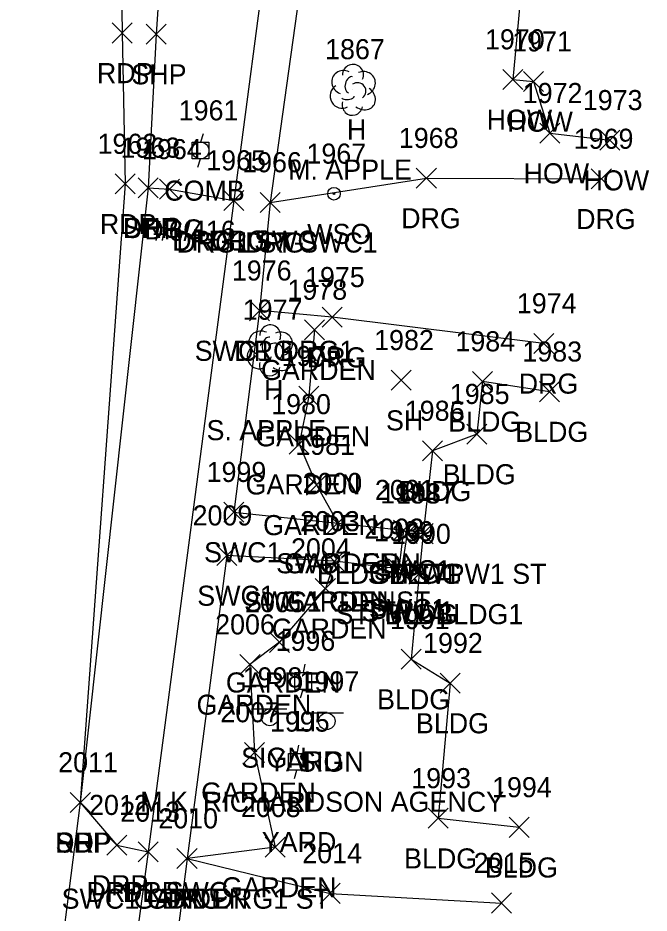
# Model space of a CAD drawing. Extents: x 1651305 to 1654558, y 539481 to 548441.
# Drawn here: x 1654391.1 to 1654454.1, y 544348.7 to 544437.8 of the extents above; entities that cross this region are included whole.
import ezdxf

# ---------------------------------------------------------------- set-up
doc = ezdxf.new("R2010")
doc.units = 0
for name, color, linetype in [('L_A', 7, 'Continuous'), ('L_C', 7, 'Continuous'), ('L_I', 7, 'Continuous'), ('L_TIC', 7, 'Continuous'), ('LAPB', 7, 'Continuous'), ('LBC', 7, 'Continuous'), ('LBF', 7, 'Continuous'), ('LTD', 7, 'Continuous'), ('P_A', 7, 'Continuous'), ('P_I', 7, 'Continuous'), ('P_TIC', 7, 'Continuous'), ('PET', 7, 'Continuous'), ('PSP', 7, 'Continuous'), ('R_A', 7, 'Continuous'), ('R_I', 7, 'Continuous'), ('R_TIC', 7, 'Continuous'), ('RDG', 7, 'Continuous'), ('RDP', 7, 'Continuous'), ('RSW', 7, 'Continuous'), ('S_A', 7, 'Continuous'), ('S_C', 7, 'Continuous'), ('S_I', 7, 'Continuous'), ('SSGN', 7, 'Continuous'), ('U_A', 7, 'Continuous'), ('U_C', 7, 'Continuous'), ('U_I', 7, 'Continuous'), ('ULP', 7, 'Continuous'), ('UP', 7, 'Continuous'), ('UWV', 7, 'Continuous')]:
    doc.layers.add(name, color=color, linetype=linetype)

msp = doc.modelspace()

# ---------------------------------------------------------------- linework, layer by layer
at = {"layer": 'L_TIC'}
for points in [[(1654439.479, 544430.714), (1654441.479, 544432.714)], [(1654441.479, 544430.714), (1654439.479, 544432.714)], [(1654441.535, 544430.51), (1654443.535, 544432.51)], [(1654443.535, 544430.51), (1654441.535, 544432.51)], [(1654443.157, 544425.366), (1654445.157, 544427.366)], [(1654445.157, 544425.366), (1654443.157, 544427.366)], [(1654449.144, 544424.661), (1654451.144, 544426.661)], [(1654451.144, 544424.661), (1654449.144, 544426.661)], [(1654419.708, 544405.771), (1654421.708, 544407.771)], [(1654421.708, 544405.771), (1654419.708, 544407.771)], [(1654428.347, 544400.756), (1654430.347, 544402.756)], [(1654430.347, 544400.756), (1654428.347, 544402.756)], [(1654436.446, 544400.633), (1654438.446, 544402.633)], [(1654438.446, 544400.633), (1654436.446, 544402.633)], [(1654419.132, 544399.165), (1654421.132, 544401.165)], [(1654421.132, 544399.165), (1654419.132, 544401.165)], [(1654443.12, 544399.614), (1654445.12, 544401.614)], [(1654445.12, 544399.614), (1654443.12, 544401.614)], [(1654435.894, 544395.387), (1654437.894, 544397.387)], [(1654437.894, 544395.387), (1654435.894, 544397.387)], [(1654418.173, 544394.372), (1654420.173, 544396.372)], [(1654420.173, 544394.372), (1654418.173, 544396.372)], [(1654431.456, 544393.71), (1654433.456, 544395.71)], [(1654433.456, 544393.71), (1654431.456, 544395.71)], [(1654419.916, 544390.32), (1654421.916, 544392.32)], [(1654421.916, 544390.32), (1654419.916, 544392.32)], [(1654422.018, 544386.519), (1654424.018, 544388.519)], [(1654424.018, 544386.519), (1654422.018, 544388.519)], [(1654428.943, 544385.479), (1654430.943, 544387.479)], [(1654430.943, 544385.479), (1654428.943, 544387.479)], [(1654430.537, 544385.471), (1654432.537, 544387.471)], [(1654432.537, 544385.471), (1654430.537, 544387.471)], [(1654430.537, 544385.471), (1654432.537, 544387.471)], [(1654432.537, 544385.471), (1654430.537, 544387.471)], [(1654421.687, 544382.714), (1654423.687, 544384.714)], [(1654423.687, 544382.714), (1654421.687, 544384.714)], [(1654428.343, 544381.719), (1654430.343, 544383.719)], [(1654430.343, 544381.719), (1654428.343, 544383.719)], [(1654430.125, 544381.453), (1654432.125, 544383.453)], [(1654432.125, 544381.453), (1654430.125, 544383.453)], [(1654430.125, 544381.453), (1654432.125, 544383.453)], [(1654432.125, 544381.453), (1654430.125, 544383.453)], [(1654420.789, 544380.007), (1654422.789, 544382.007)], [(1654422.789, 544380.007), (1654420.789, 544382.007)], [(1654416.206, 544374.646), (1654418.206, 544376.646)], [(1654418.206, 544374.646), (1654416.206, 544376.646)], [(1654413.279, 544372.431), (1654415.279, 544374.431)], [(1654415.279, 544372.431), (1654413.279, 544374.431)], [(1654429.354, 544372.968), (1654431.354, 544374.968)], [(1654431.354, 544372.968), (1654429.354, 544374.968)], [(1654433.226, 544370.582), (1654435.226, 544372.582)], [(1654435.226, 544370.582), (1654433.226, 544372.582)], [(1654413.737, 544363.68), (1654415.737, 544365.68)], [(1654415.737, 544363.68), (1654413.737, 544365.68)], [(1654432.046, 544357.115), (1654434.046, 544359.115)], [(1654434.046, 544357.115), (1654432.046, 544359.115)], [(1654440.097, 544356.215), (1654442.097, 544358.215)], [(1654442.097, 544356.215), (1654440.097, 544358.215)], [(1654415.795, 544354.239), (1654417.795, 544356.239)], [(1654417.795, 544354.239), (1654415.795, 544356.239)], [(1654407, 544353.107), (1654409, 544355.107)], [(1654409, 544353.107), (1654407, 544355.107)]]:
    msp.add_lwpolyline(points, dxfattribs=at)
at = {"layer": 'LAPB'}
for points in [[(1654420.708, 544406.771), (1654420.132, 544400.165), (1654419.173, 544395.372), (1654420.916, 544391.32), (1654423.018, 544387.519)], [(1654422.687, 544383.714), (1654421.789, 544381.007), (1654417.206, 544375.646), (1654414.279, 544373.431), (1654414.737, 544364.68), (1654416.795, 544355.239), (1654408, 544354.107)]]:
    msp.add_lwpolyline(points, dxfattribs=at)
at = {"layer": 'LBC'}
for points in [[(1654450.965, 544465.468), (1654444.011, 544466.184), (1654442.811, 544454.213), (1654441.59, 544443.825), (1654440.479, 544431.714), (1654442.535, 544431.51), (1654444.157, 544426.366), (1654450.144, 544425.661)], [(1654444.12, 544400.614), (1654437.446, 544401.633), (1654436.894, 544396.387), (1654432.456, 544394.71), (1654431.537, 544386.471), (1654431.125, 544382.453), (1654430.354, 544373.968), (1654434.226, 544371.582), (1654433.046, 544358.115), (1654441.097, 544357.215)]]:
    msp.add_lwpolyline(points, dxfattribs=at)
at = {"layer": 'LBF'}
msp.add_lwpolyline([(1654431.537, 544386.471), (1654429.943, 544386.479), (1654429.343, 544382.719), (1654431.125, 544382.453)], dxfattribs=at)
at = {"layer": 'LTD'}
for p, q in [((1654424.505, 544430.733), (1654424.505, 544430.733)), ((1654424.505, 544430.733), (1654424.505, 544430.733)), ((1654416.25, 544404.781), (1654416.25, 544404.781)), ((1654416.25, 544404.781), (1654416.25, 544404.781))]:
    msp.add_line(p, q, dxfattribs=at)
for centre in [(1654424.552, 544432.167), (1654416.296, 544406.215)]:
    msp.add_arc(centre, 1.047, 335.52715, 180.95627, dxfattribs=at)
for centre, major_axis, ratio, start_param, end_param in [((1654423.713, 544431.399), (1.21, -0.512), 0.895232, 1.570796, 4.712389), ((1654425.547, 544431.316), (-1.141, -0.483), 0.949671, 1.570796, 4.712389), ((1654424.297, 544431.191), (-0.208, -0.792), 0.645439, 3.141593, 6.283185), ((1654425.005, 544430.566), (-0.5, 0.667), 0.989748, 3.141593, 6.283185), ((1654423.422, 544430.024), (0.584, -1.042), 0.959034, 3.141593, 6.283185), ((1654425.505, 544429.9), (-1.09, 0.792), 0.841452, 1.570796, 4.712389), ((1654424.047, 544429.983), (-0.625, -0.083), 0.423636, 0, 3.141593), ((1654424.505, 544429.233), (0.265, 1.061), 0.942809, 1.570796, 4.712389), ((1654415.458, 544405.448), (1.21, -0.512), 0.895232, 1.570796, 4.712389), ((1654417.291, 544405.365), (-1.141, -0.483), 0.949671, 1.570796, 4.712389), ((1654416.041, 544405.24), (-0.208, -0.792), 0.645439, 3.141593, 6.283185), ((1654415.166, 544404.073), (0.584, -1.042), 0.959034, 3.141593, 6.283185), ((1654416.75, 544404.615), (-0.5, 0.667), 0.989748, 3.141593, 6.283185), ((1654417.25, 544403.948), (-1.09, 0.792), 0.841452, 1.570796, 4.712389), ((1654415.791, 544404.031), (-0.625, -0.083), 0.423636, 0, 3.141593), ((1654416.25, 544403.281), (0.265, 1.061), 0.942809, 1.570796, 4.712389)]:
    msp.add_ellipse(centre, major_axis=major_axis, ratio=ratio, start_param=start_param, end_param=end_param, dxfattribs=at)
at = {"layer": 'P_TIC'}
for points in [[(1654400.531, 544435.346), (1654402.531, 544437.346)], [(1654402.531, 544435.346), (1654400.531, 544437.346)], [(1654403.923, 544435.226), (1654405.923, 544437.226)], [(1654405.923, 544435.226), (1654403.923, 544437.226)], [(1654400.825, 544420.309), (1654402.825, 544422.309)], [(1654402.825, 544420.309), (1654400.825, 544422.309)], [(1654403.117, 544419.923), (1654405.117, 544421.923)], [(1654405.117, 544419.923), (1654403.117, 544421.923)], [(1654396.366, 544358.696), (1654398.366, 544360.696)], [(1654398.366, 544358.696), (1654396.366, 544360.696)], [(1654396.366, 544358.696), (1654398.366, 544360.696)], [(1654398.366, 544358.696), (1654396.366, 544360.696)]]:
    msp.add_lwpolyline(points, dxfattribs=at)
at = {"layer": 'PET'}
msp.add_lwpolyline([(1654345.042, 544588.36), (1654350.59, 544607.191), (1654356.582, 544624.309), (1654366.692, 544597.705), (1654378.699, 544565.627), (1654388.798, 544536.019), (1654394.392, 544506.433), (1654399.121, 544481.008), (1654401.125, 544462.893), (1654401.531, 544436.346), (1654401.825, 544421.309), (1654397.366, 544359.696), (1654394.392, 544336.586), (1654391.404, 544308.963), (1654388.941, 544290.736), (1654386.845, 544274.06), (1654380.974, 544229.445), (1654377.749, 544202.908), (1654375.628, 544181.037), (1654372.192, 544149.754), (1654366.612, 544105.723), (1654362.798, 544072.788)], dxfattribs=at)
at = {"layer": 'PSP'}
msp.add_lwpolyline([(1654388.798, 544536.019), (1654393.152, 544530.334), (1654397.052, 544530.18), (1654401.661, 544509.48), (1654405.45, 544481.191), (1654406.951, 544466.687), (1654404.923, 544436.226), (1654404.117, 544420.923), (1654397.366, 544359.696)], dxfattribs=at)
at = {"layer": 'R_TIC'}
for points in [[(1654430.857, 544420.889), (1654432.857, 544422.889)], [(1654432.857, 544420.889), (1654430.857, 544422.889)], [(1654448.296, 544420.81), (1654450.296, 544422.81)], [(1654450.296, 544420.81), (1654448.296, 544422.81)], [(1654403.117, 544419.923), (1654405.117, 544421.923)], [(1654405.117, 544419.923), (1654403.117, 544421.923)], [(1654405.26, 544419.775), (1654407.26, 544421.775)], [(1654407.26, 544419.775), (1654405.26, 544421.775)], [(1654411.659, 544418.662), (1654413.659, 544420.662)], [(1654413.659, 544418.662), (1654411.659, 544420.662)], [(1654411.659, 544418.662), (1654413.659, 544420.662)], [(1654413.659, 544418.662), (1654411.659, 544420.662)], [(1654415.298, 544418.47), (1654417.298, 544420.47)], [(1654417.298, 544418.47), (1654415.298, 544420.47)], [(1654415.298, 544418.47), (1654417.298, 544420.47)], [(1654417.298, 544418.47), (1654415.298, 544420.47)], [(1654414.224, 544407.685), (1654416.224, 544409.685)], [(1654416.224, 544407.685), (1654414.224, 544409.685)], [(1654414.224, 544407.685), (1654416.224, 544409.685)], [(1654416.224, 544407.685), (1654414.224, 544409.685)], [(1654421.456, 544407.031), (1654423.456, 544409.031)], [(1654423.456, 544407.031), (1654421.456, 544409.031)], [(1654442.572, 544404.42), (1654444.572, 544406.42)], [(1654444.572, 544404.42), (1654442.572, 544406.42)], [(1654411.657, 544387.617), (1654413.657, 544389.617)], [(1654413.657, 544387.617), (1654411.657, 544389.617)], [(1654422.018, 544386.519), (1654424.018, 544388.519)], [(1654424.018, 544386.519), (1654422.018, 544388.519)], [(1654428.579, 544385.827), (1654430.579, 544387.827)], [(1654430.579, 544385.827), (1654428.579, 544387.827)], [(1654410.983, 544383.286), (1654412.983, 544385.286)], [(1654412.983, 544383.286), (1654410.983, 544385.286)], [(1654421.687, 544382.714), (1654423.687, 544384.714)], [(1654423.687, 544382.714), (1654421.687, 544384.714)], [(1654428.097, 544381.97), (1654430.097, 544383.97)], [(1654430.097, 544381.97), (1654428.097, 544383.97)], [(1654396.366, 544358.696), (1654398.366, 544360.696)], [(1654398.366, 544358.696), (1654396.366, 544360.696)], [(1654400.014, 544354.446), (1654402.014, 544356.446)], [(1654402.014, 544354.446), (1654400.014, 544356.446)], [(1654403.122, 544353.774), (1654405.122, 544355.774)], [(1654405.122, 544353.774), (1654403.122, 544355.774)], [(1654403.122, 544353.774), (1654405.122, 544355.774)], [(1654405.122, 544353.774), (1654403.122, 544355.774)], [(1654407, 544353.107), (1654409, 544355.107)], [(1654409, 544353.107), (1654407, 544355.107)], [(1654407, 544353.107), (1654409, 544355.107)], [(1654409, 544353.107), (1654407, 544355.107)], [(1654421.263, 544349.637), (1654423.263, 544351.637)], [(1654423.263, 544349.637), (1654421.263, 544351.637)], [(1654438.341, 544348.676), (1654440.341, 544350.676)], [(1654440.341, 544348.676), (1654438.341, 544350.676)]]:
    msp.add_lwpolyline(points, dxfattribs=at)
at = {"layer": 'RDG'}
for points in [[(1654416.298, 544419.47), (1654431.857, 544421.889), (1654449.296, 544421.81)], [(1654404.117, 544420.923), (1654406.26, 544420.775), (1654412.659, 544419.662)], [(1654443.572, 544405.42), (1654422.456, 544408.031), (1654415.224, 544408.685)], [(1654408, 544354.107), (1654422.263, 544350.637), (1654439.341, 544349.676)]]:
    msp.add_lwpolyline(points, dxfattribs=at)
at = {"layer": 'RDP'}
msp.add_lwpolyline([(1654397.366, 544359.696), (1654401.014, 544355.446), (1654404.122, 544354.774)], dxfattribs=at)
at = {"layer": 'RSW'}
for points in [[(1654407.404, 544661.775), (1654407.293, 544658.868), (1654407.962, 544657.877), (1654443.269, 544654.592), (1654438.81, 544619.894), (1654433.558, 544580.17), (1654430.136, 544553.995), (1654428.025, 544537.281), (1654424.833, 544512.838), (1654419.77, 544473.615), (1654412.659, 544419.662), (1654404.122, 544354.774), (1654402.102, 544339.773), (1654395.487, 544286.058), (1654394.013, 544276.122), (1654388.386, 544229.583), (1654383.891, 544196.376), (1654382.201, 544184.333), (1654378.352, 544149.148), (1654372.361, 544105.495), (1654368.546, 544072.052)], [(1654433.769, 544447.317), (1654420.392, 544448.732), (1654416.298, 544419.47), (1654415.224, 544408.685), (1654412.657, 544388.617), (1654423.018, 544387.519), (1654429.579, 544386.827), (1654429.097, 544382.97), (1654422.687, 544383.714), (1654411.983, 544384.286), (1654408, 544354.107), (1654405.993, 544338.287), (1654403.211, 544318.213), (1654402.851, 544314.962), (1654399.432, 544285.106), (1654398.089, 544275.966), (1654392.335, 544231.256), (1654397.808, 544230.762), (1654412.219, 544229.296)]]:
    msp.add_lwpolyline(points, dxfattribs=at)
at = {"layer": 'SSGN'}
for p, q in [((1654414.608, 544369.007), (1654417.942, 544369.007)), ((1654416.255, 544368.173), (1654416.255, 544368.173)), ((1654420.281, 544368.612), (1654423.614, 544368.612)), ((1654421.928, 544367.779), (1654421.928, 544367.779))]:
    msp.add_line(p, q, dxfattribs=at)
for centre in [(1654416.255, 544368.173), (1654421.928, 544367.779)]:
    msp.add_circle(centre, 0.833, dxfattribs=at)
at = {"layer": 'ULP'}
for p, q in [((1654418.745, 544370.958), (1654418.745, 544372.624)), ((1654418.745, 544372.624), (1654420.412, 544372.624)), ((1654419.745, 544373.458), (1654419.578, 544372.624)), ((1654420.412, 544372.624), (1654420.412, 544370.958)), ((1654419.578, 544371.791), (1654419.578, 544371.791)), ((1654420.412, 544370.958), (1654418.745, 544370.958)), ((1654419.328, 544370.124), (1654419.578, 544370.958)), ((1654418.125, 544362.911), (1654418.125, 544364.578)), ((1654418.125, 544364.578), (1654419.792, 544364.578)), ((1654419.125, 544365.411), (1654418.959, 544364.578)), ((1654419.792, 544364.578), (1654419.792, 544362.911)), ((1654418.959, 544363.745), (1654418.959, 544363.745)), ((1654419.792, 544362.911), (1654418.125, 544362.911)), ((1654418.709, 544362.078), (1654418.959, 544362.911))]:
    msp.add_line(p, q, dxfattribs=at)
at = {"layer": 'UP'}
for p, q in [((1654409.596, 544426.306), (1654409.346, 544425.473)), ((1654408.513, 544423.806), (1654408.513, 544425.473)), ((1654408.513, 544425.473), (1654410.179, 544425.473)), ((1654410.179, 544425.473), (1654410.179, 544423.806)), ((1654409.346, 544424.64), (1654409.346, 544424.64)), ((1654410.179, 544423.806), (1654408.513, 544423.806)), ((1654409.096, 544422.973), (1654409.346, 544423.806))]:
    msp.add_line(p, q, dxfattribs=at)
msp.add_circle((1654409.346, 544424.64), 0.833, dxfattribs=at)
at = {"layer": 'UWV'}
for radius in [0.625, 0.0833]:
    msp.add_circle((1654422.647, 544420.329), radius, dxfattribs=at)

# ---------------------------------------------------------------- texts
at = {"layer": 'L_A'}
for s, p in [('HOW', (1654437.864, 544426.714)), ('HOW', (1654439.921, 544426.51)), ('H', (1654423.938, 544425.733)), ('HOW', (1654441.543, 544421.366)), ('HOW', (1654447.53, 544420.661)), ('GARDEN', (1654415.377, 544401.771)), ('H', (1654415.683, 544399.781)), ('SH', (1654427.835, 544396.756)), ('BLDG', (1654434.036, 544396.633)), ('BLDG', (1654440.711, 544395.614)), ('GARDEN', (1654414.801, 544395.165)), ('BLDG', (1654433.484, 544391.387)), ('GARDEN', (1654413.842, 544390.372)), ('BLDG', (1654429.046, 544389.71)), ('GARDEN', (1654415.586, 544386.32)), ('GARDEN', (1654417.687, 544382.519)), ('BLDG1 STPW1 ST', (1654420.947, 544381.471)), ('STPW1', (1654426.006, 544381.479)), ('BLDG', (1654428.128, 544381.471)), ('GARDEN', (1654417.356, 544378.714)), ('STPW1', (1654425.406, 544377.719)), ('STPW1 BLDG1', (1654422.795, 544377.453)), ('BLDG', (1654427.716, 544377.453)), ('GARDEN', (1654416.458, 544376.007)), ('GARDEN', (1654411.875, 544370.646)), ('BLDG', (1654426.944, 544368.968)), ('GARDEN', (1654408.949, 544368.431)), ('BLDG', (1654430.816, 544366.582)), ('GARDEN', (1654409.406, 544359.68)), ('BLDG', (1654429.636, 544353.115)), ('BLDG', (1654437.687, 544352.215)), ('GARDEN', (1654411.464, 544350.239)), ('GARDEN', (1654402.669, 544349.107))]:
    msp.add_text(s, height=2, dxfattribs=at).set_placement(p)
at = {"layer": 'L_C'}
for s, p in [('M. APPLE', (1654418.08, 544421.733)), ('S. APPLE', (1654409.95, 544395.781))]:
    msp.add_text(s, height=2, dxfattribs=at).set_placement(p)
at = {"layer": 'L_I'}
for s, p in [('1970', (1654437.699, 544434.714)), ('1971', (1654440.409, 544434.51)), ('1867', (1654421.765, 544433.733)), ('1972', (1654441.465, 544429.366)), ('1973', (1654447.452, 544428.661)), ('1978', (1654418.015, 544409.771)), ('1977', (1654413.557, 544407.781)), ('1982', (1654426.654, 544404.756)), ('1984', (1654434.753, 544404.633)), ('1983', (1654441.427, 544403.614)), ('1979', (1654417.431, 544403.165)), ('1985', (1654434.201, 544399.387)), ('1980', (1654416.394, 544398.372)), ('1986', (1654429.708, 544397.71)), ('1981', (1654418.791, 544394.32)), ('2000', (1654419.514, 544390.519)), ('1988', (1654427.25, 544389.479)), ('1987', (1654428.845, 544389.471)), ('1987', (1654428.845, 544389.471)), ('2003', (1654419.27, 544386.714)), ('1989', (1654426.643, 544385.719)), ('1990', (1654428.346, 544385.453)), ('1990', (1654428.346, 544385.453)), ('2004', (1654418.371, 544384.007)), ('2005', (1654413.789, 544378.646)), ('1991', (1654428.228, 544376.968)), ('2006', (1654410.807, 544376.431)), ('1992', (1654431.533, 544374.582)), ('2007', (1654411.319, 544367.68)), ('1993', (1654430.353, 544361.115)), ('1994', (1654438.404, 544360.215)), ('2008', (1654413.378, 544358.239)), ('2010', (1654405.142, 544357.107))]:
    msp.add_text(s, height=2, dxfattribs=at).set_placement(p)
at = {"layer": 'P_A'}
for s, p in [('RDP', (1654399.019, 544431.346)), ('SHP', (1654402.458, 544431.226)), ('RDP', (1654399.314, 544416.309)), ('SHP', (1654401.653, 544415.923)), ('SHP', (1654394.901, 544354.696)), ('RDP', (1654394.854, 544354.696))]:
    msp.add_text(s, height=2, dxfattribs=at).set_placement(p)
at = {"layer": 'P_I'}
for s, p in [('1962', (1654399.085, 544424.309)), ('1963', (1654401.377, 544423.923)), ('2011', (1654395.161, 544362.696)), ('2011', (1654395.161, 544362.696))]:
    msp.add_text(s, height=2, dxfattribs=at).set_placement(p)
at = {"layer": 'R_A'}
for s, p in [('DRG', (1654429.345, 544416.889)), ('DRG', (1654446.784, 544416.81)), ('DRG', (1654401.606, 544415.923)), ('DRG', (1654403.748, 544415.775)), ('DRG1 SWC', (1654406.525, 544414.662)), ('DRG1 ST SWC1', (1654406.944, 544414.47)), ('DRG', (1654410.147, 544414.662)), ('DRG', (1654413.786, 544414.47)), ('SWC1 DRG1', (1654408.768, 544403.685)), ('DRG', (1654412.712, 544403.685)), ('DRG', (1654419.944, 544403.031)), ('DRG', (1654441.06, 544400.42)), ('SWC1', (1654409.696, 544383.617)), ('SWC1 GDN', (1654416.884, 544382.519)), ('SWC1', (1654426.618, 544381.827)), ('SWC1', (1654409.022, 544379.286)), ('SWC1 GDN ST', (1654413.687, 544378.714)), ('SWC1', (1654426.136, 544377.97)), ('DRP', (1654394.854, 544354.696)), ('DRP', (1654398.502, 544350.446)), ('DRP1 SWC', (1654397.989, 544349.774)), ('DRP', (1654401.611, 544349.774)), ('SWC1 GDN DRG1 ST', (1654395.504, 544349.107)), ('DRG', (1654405.488, 544349.107))]:
    msp.add_text(s, height=2, dxfattribs=at).set_placement(p)
at = {"layer": 'R_I'}
for s, p in [('1968', (1654429.117, 544424.889)), ('1969', (1654446.548, 544424.81)), ('1963', (1654401.377, 544423.923)), ('1964', (1654403.52, 544423.775)), ('1965', (1654409.919, 544422.662)), ('1965', (1654409.919, 544422.662)), ('1966', (1654413.503, 544422.47)), ('1966', (1654413.503, 544422.47)), ('1976', (1654412.476, 544411.685)), ('1976', (1654412.476, 544411.685)), ('1975', (1654419.763, 544411.031)), ('1974', (1654440.879, 544408.42)), ('1999', (1654409.956, 544391.617)), ('2000', (1654419.514, 544390.519)), ('2001', (1654426.728, 544389.827)), ('2009', (1654408.558, 544387.286)), ('2003', (1654419.27, 544386.714)), ('2002', (1654425.68, 544385.97)), ('2011', (1654395.161, 544362.696)), ('2012', (1654398.242, 544358.446)), ('2013', (1654401.351, 544357.774)), ('2013', (1654401.351, 544357.774)), ('2010', (1654405.142, 544357.107)), ('2010', (1654405.142, 544357.107)), ('2014', (1654419.492, 544353.637)), ('2015', (1654436.57, 544352.676))]:
    msp.add_text(s, height=2, dxfattribs=at).set_placement(p)
at = {"layer": 'S_A'}
for p in [(1654413.393, 544363.153), (1654419.066, 544362.759)]:
    msp.add_text('SIGN', height=2, dxfattribs=at).set_placement(p)
at = {"layer": 'S_C'}
msp.add_text('M.K. RICHARDSON AGENCY', height=2, dxfattribs=at).set_placement((1654403.342, 544358.759))
at = {"layer": 'S_I'}
for s, p in [('1998', (1654413.543, 544371.153)), ('1997', (1654419.216, 544370.759))]:
    msp.add_text(s, height=2, dxfattribs=at).set_placement(p)
at = {"layer": 'U_A'}
for s, p in [('COMB', (1654405.732, 544419.64)), ('WSO', (1654419.978, 544415.329)), ('LI', (1654418.681, 544366.791)), ('LI', (1654418.061, 544358.745))]:
    msp.add_text(s, height=2, dxfattribs=at).set_placement(p)
at = {"layer": 'U_C'}
for s, p in [('#6/416', (1654404.677, 544415.64)), ('YARD', (1654416.074, 544362.791)), ('YARD', (1654415.455, 544354.745))]:
    msp.add_text(s, height=2, dxfattribs=at).set_placement(p)
at = {"layer": 'U_I'}
for s, p in [('1961', (1654407.173, 544427.64)), ('1967', (1654419.907, 544423.329)), ('1996', (1654416.831, 544374.791)), ('1995', (1654416.266, 544366.745))]:
    msp.add_text(s, height=2, dxfattribs=at).set_placement(p)

doc.saveas('drawing.dxf')
